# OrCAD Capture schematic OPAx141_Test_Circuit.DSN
size A; title: Single-Supply, 10MHz, Rail-to-Rail Output, Low-Noise, JFET; rev: 1.5; note: Datasheet: SBOS510B  EVM: N/A
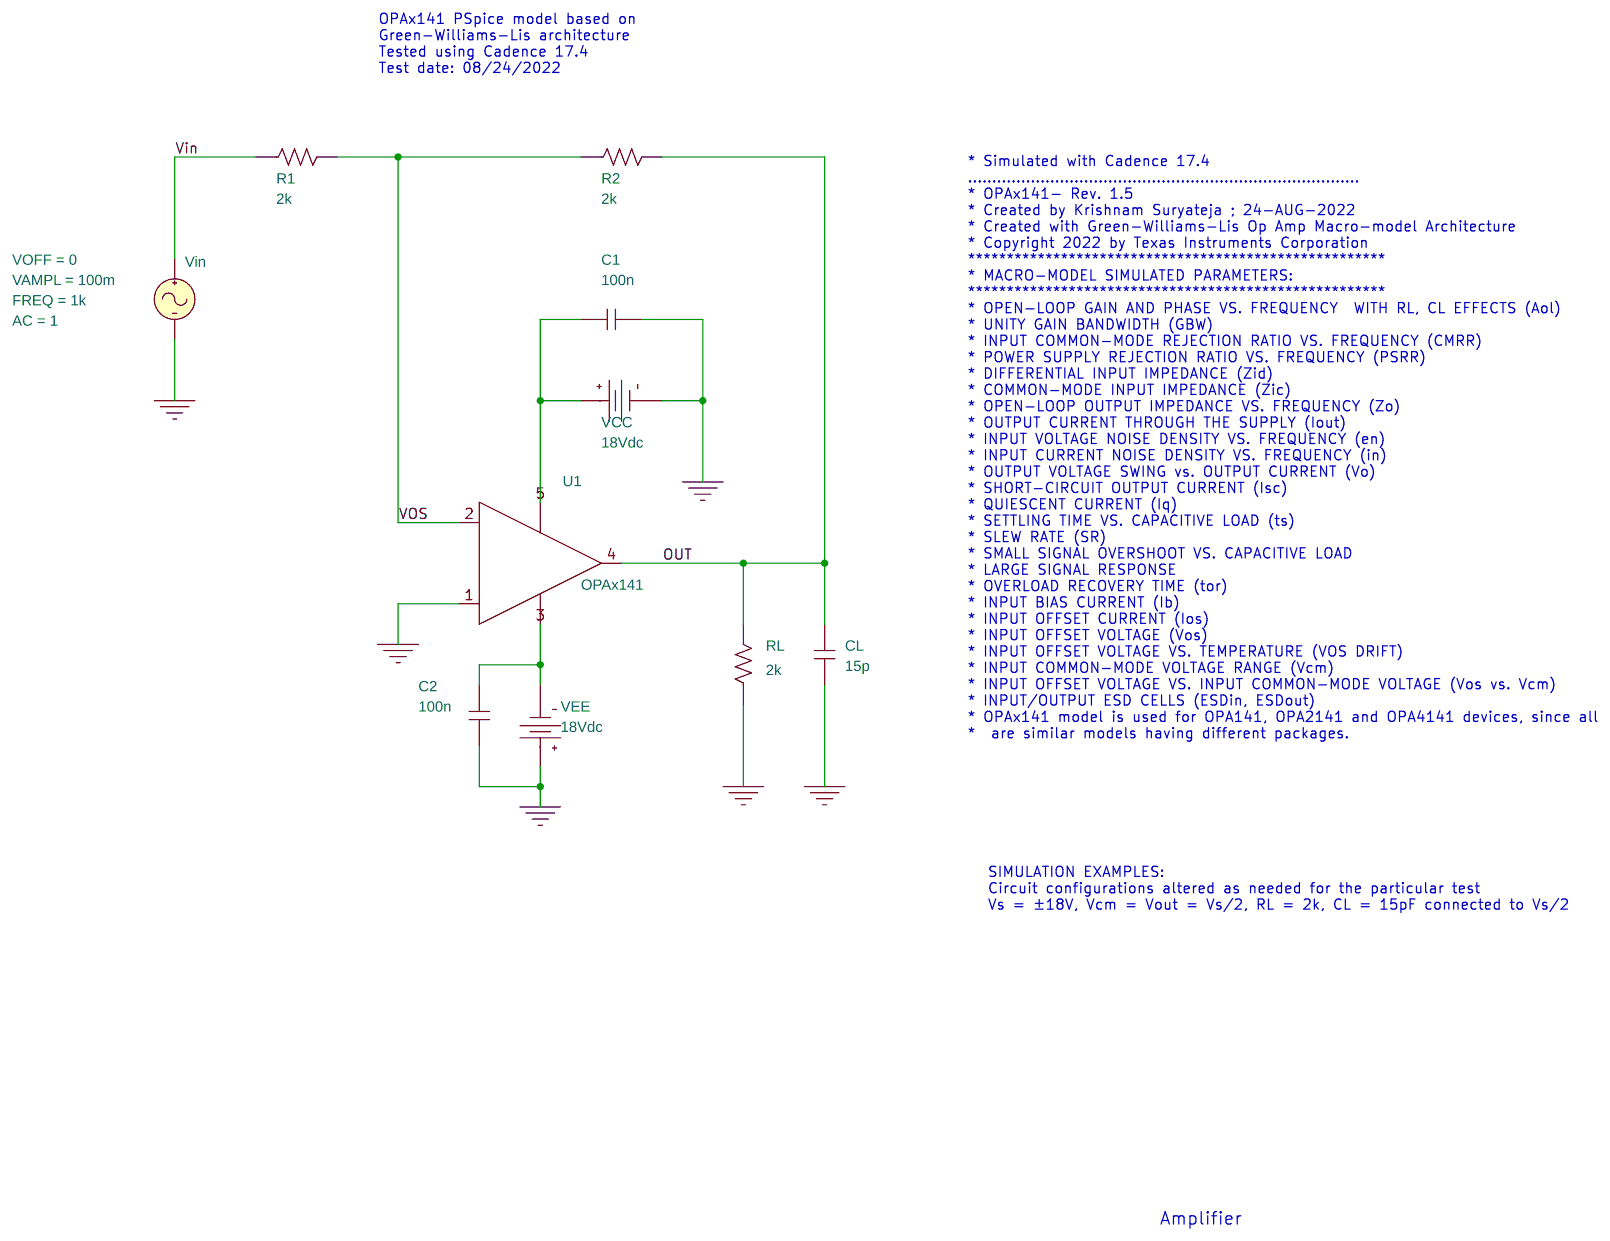
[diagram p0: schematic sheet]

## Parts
C1  100n  [cap196]
C2  100n  [cap196]
CL  15p  [RAD/CK05]
R1  2k  [AXRC05]
R2  2k  [AXRC05]
RL  2k  [AXRC05]
U1  OPAx141
VCC  VDC
VEE  VDC
Vin  VSIN

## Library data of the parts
C1 C2 CL = C
R1 R2 RL = R
U1 = OPAx141
VCC VEE = VDC: DC: 18Vdc
Vin = VSIN: AC: 1; FREQ: 1k; VAMPL: 100m; VOFF: 0

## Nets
Vin: R1.1 Vin.1(+)
0: C1.2 C2.1 CL.1 RL.1 U1.1(+) VCC.1(-) VEE.0(+) Vin.2(-)
OUT: CL.2 R2.2 RL.2 U1.4(OUT)
VOS: R1.2 R2.1 U1.2(-)
N27303: C1.1 U1.5(V+) VCC.0(+)
N27376: C2.2 U1.3(V-) VEE.1(-)

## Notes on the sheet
- OPAx141 PSpice model based on
  Green-Williams-Lis architecture
  Tested using Cadence 17.4
  Test date: 08/24/2022
- * Simulated with Cadence 17.4
  .................................................................................
  * OPAx141- Rev. 1.5
  * Created by Krishnam Suryateja ; 24-AUG-2022
  * Created with Green-Williams-Lis Op Amp Macro-model Architecture
  * Copyright 2022 by Texas Instruments Corporation
  ******************************************************
  * MACRO-MODEL SIMULATED PARAMETERS:
  ******************************************************
  * OPEN-LOOP GAIN AND PHASE VS. FREQUENCY  WITH RL, CL EFFECTS (Aol)
  * UNITY GAIN BANDWIDTH (GBW)
  * INPUT COMMON-MODE REJECTION RATIO VS. FREQUENCY (CMRR)
  * POWER SUPPLY REJECTION RATIO VS. FREQUENCY (PSRR)
  * DIFFERENTIAL INPUT IMPEDANCE (Zid)
  * COMMON-MODE INPUT IMPEDANCE (Zic)
  * OPEN-LOOP OUTPUT IMPEDANCE VS. FREQUENCY (Zo)
  * OUTPUT CURRENT THROUGH THE SUPPLY (Iout)
  * INPUT VOLTAGE NOISE DENSITY VS. FREQUENCY (en)
  * INPUT CURRENT NOISE DENSITY VS. FREQUENCY (in)
  * OUTPUT VOLTAGE SWING vs. OUTPUT CURRENT (Vo)
  * SHORT-CIRCUIT OUTPUT CURRENT (Isc)
  * QUIESCENT CURRENT (Iq)
  * SETTLING TIME VS. CAPACITIVE LOAD (ts)
  * SLEW RATE (SR)
  * SMALL SIGNAL OVERSHOOT VS. CAPACITIVE LOAD
  * LARGE SIGNAL RESPONSE
  * OVERLOAD RECOVERY TIME (tor)
  * INPUT BIAS CURRENT (Ib)
  * INPUT OFFSET CURRENT (Ios)
  * INPUT OFFSET VOLTAGE (Vos)
  * INPUT OFFSET VOLTAGE VS. TEMPERATURE (VOS DRIFT)
  * INPUT COMMON-MODE VOLTAGE RANGE (Vcm)
  * INPUT OFFSET VOLTAGE VS. INPUT COMMON-MODE VOLTAGE (Vos vs. Vcm)
  * INPUT/OUTPUT ESD CELLS (ESDin, ESDout)
  * OPAx141 model is used for OPA141, OPA2141 and OPA4141 devices, since all
  *  are similar models having different packages.
- SIMULATION EXAMPLES:
  Circuit configurations altered as needed for the particular test
  Vs = ±18V, Vcm = Vout = Vs/2, RL = 2k, CL = 15pF connected to Vs/2
- Amplifier
